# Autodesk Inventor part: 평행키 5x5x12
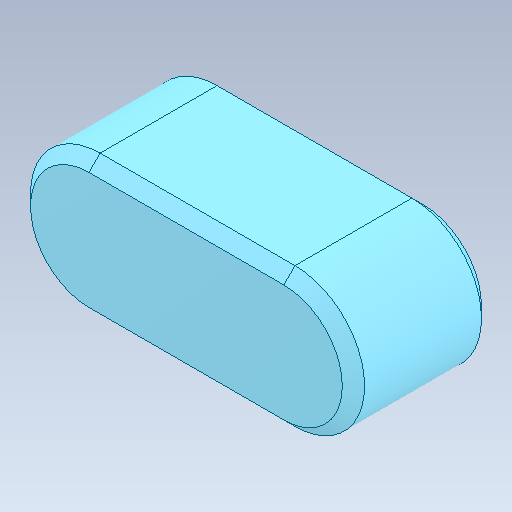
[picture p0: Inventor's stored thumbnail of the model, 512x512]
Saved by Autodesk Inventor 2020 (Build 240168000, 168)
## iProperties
Created: 2024-08
Part Number: 평행키 5x5x12
Material: 강철, 연강
Description: 키 및 해당 키홈
Document SubType Name: Modeling
Designer: oem
Density: 7.85 g/cm^3
Appearance: 기본값
Author: jhkim
Sending System: Autodesk Inventor 2025
Preprocessor: ST-DEVELOPER v20
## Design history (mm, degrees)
node "평행키 5x5x121"
node "솔리드1"
body "Solid1"
